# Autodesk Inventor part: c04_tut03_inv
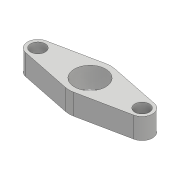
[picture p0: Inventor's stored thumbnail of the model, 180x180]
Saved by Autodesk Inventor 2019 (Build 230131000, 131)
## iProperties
Created: 2017-04
Part Number: c04_tut03_inv
Material: Generic
Document SubType Name: Modeling
Designer: CADCIM 00
Density: 1 g/cm^3
Appearance: Default
Author: CADCIM 00
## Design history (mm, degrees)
sketch "Sketch1"
  geometry: L1 (26, 4.899)-(2, 9.798); L2 (26, -4.899)-(2, -9.798); L3 (-2, 9.798)-(-26, 4.899); L4 (-2, -9.798)-(-26, -4.899); C1 r 3.5 at (25, 0); C2 r 3.5 at (-25, 0); C3 r 7.5 at (0, 0); A1 r 5 centre (-25, 0) between (-26, 4.899) and (-26, -4.899); A2 r 5 centre (25, 0) between (26, -4.899) and (26, 4.899); A3 r 10 centre (0, 0) between (-2, -9.798) and (2, -9.798); A4 r 10 centre (0, 0) between (2, 9.798) and (-2, 9.798); 1 further point
  constraints: 8 end point, 8 point on circle, 8 tangent, 7 centre point, 4 coincident, 2 equal length, 2 equal radius, 2 horizontal alignment
  dimensions: "d0" = 15 diameter of C3; "d1" = 10 radius of A4; "d2" = 50 distance of A1.centre A2.centre; "d3" = 7 diameter of C1; "d4" = 5 radius of A2
extrude "Extrusion1" new body sketch "Sketch1" distance "d5" = 10; taper "d6" = 0 deg
body "Solid1"
